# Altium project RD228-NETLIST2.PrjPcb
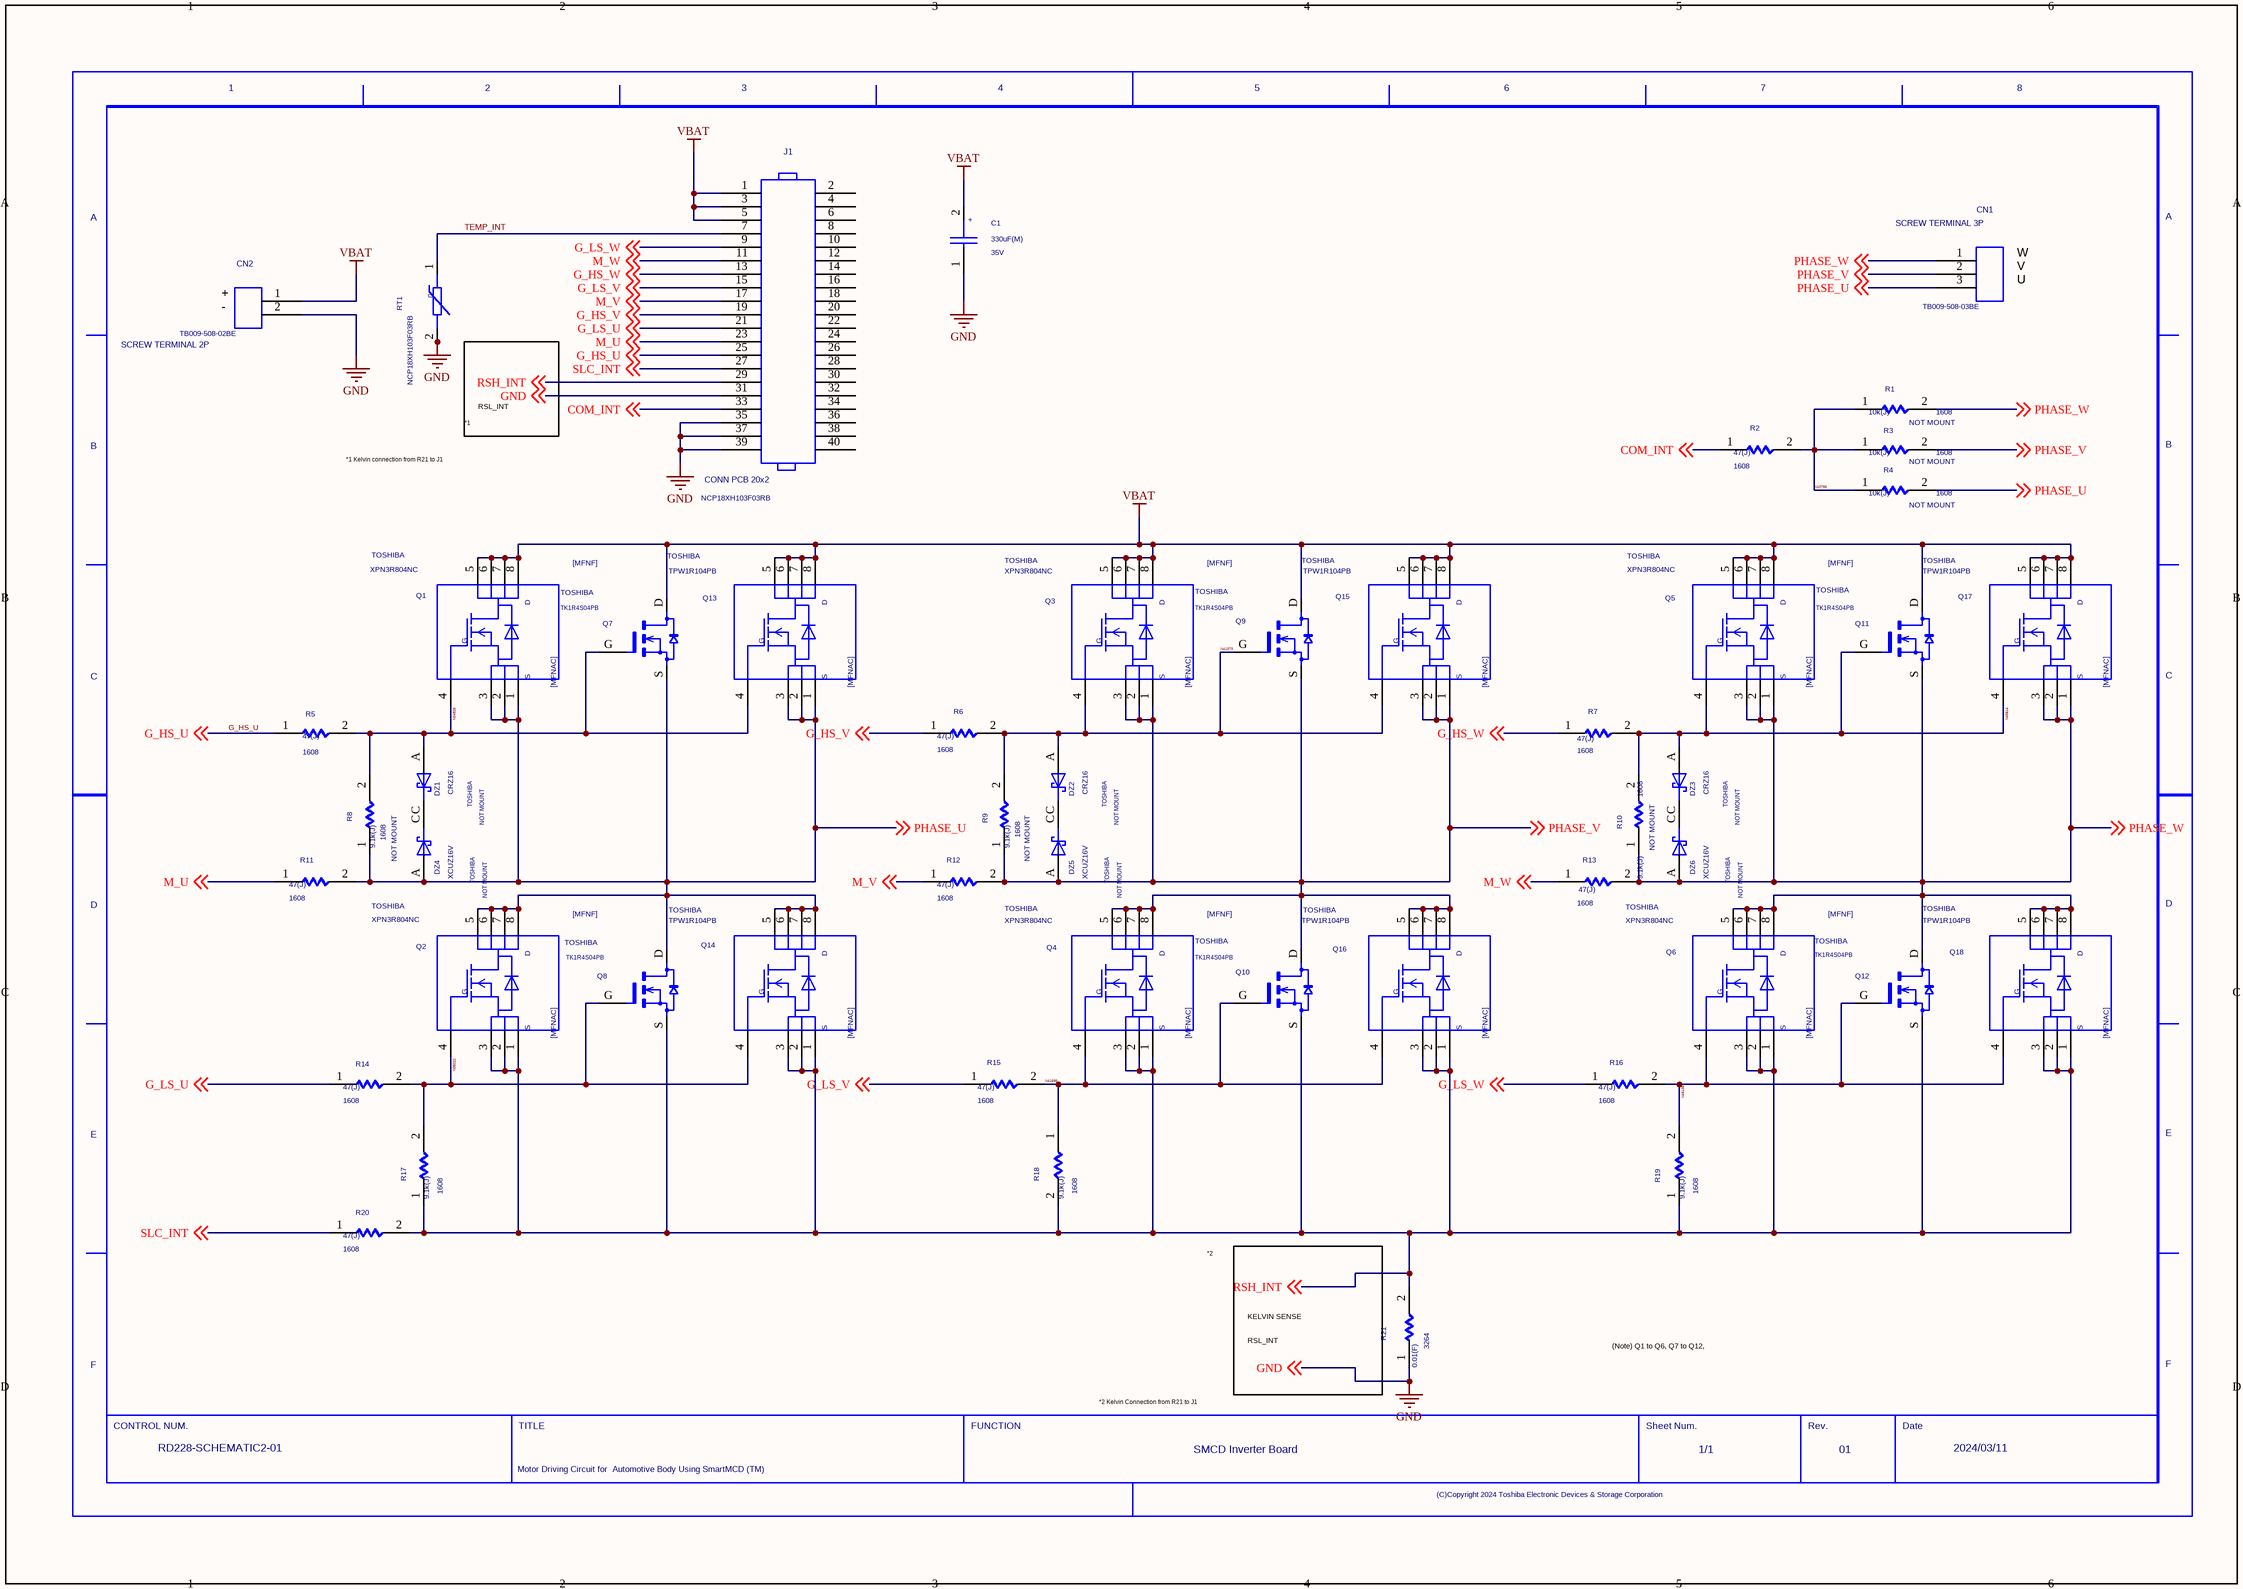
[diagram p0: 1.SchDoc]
1 sheet, 51 parts. Net scope: global (net labels, ports and power ports of the same name join across sheets).

## Sheet 1.SchDoc
size 420 x 297 mm

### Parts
C1  VAL2: 35V  VAL1: 330uF(M)  (hidden comment: CP)
CN1  SCREW TERMINAL 3P  VAL3: TB009-508-03BE
CN2  SCREW TERMINAL 2P  COMP: TB009-508-02BE
DZ1  NOTMOUNT: NOT MOUNT  USERCOMPTEXT3: TOSHIBA  VAL3: CRZ16  (hidden comment: SBD)
DZ2  NOTMOUNT: NOT MOUNT  USERCOMPTEXT3: TOSHIBA  VAL3: CRZ16  (hidden comment: SBD)
DZ3  NOTMOUNT: NOT MOUNT  USERCOMPTEXT3: TOSHIBA  VAL3: CRZ16  (hidden comment: SBD)
DZ4  NOTMOUNT: NOT MOUNT  USERCOMPTEXT3: TOSHIBA  VAL3: XCUZ16V  (hidden comment: SBD)
DZ5  NOTMOUNT: NOT MOUNT  USERCOMPTEXT3: TOSHIBA  VAL3: XCUZ16V  (hidden comment: SBD)
DZ6  NOTMOUNT: NOT MOUNT  USERCOMPTEXT3: TOSHIBA  VAL3: XCUZ16V  (hidden comment: SBD)
J1  CONN PCB 20x2  COMP: NCP18XH103F03RB
Q1  USERCOMPTEXT3: TOSHIBA  VAL3: XPN3R804NC  (hidden comment: MFNAC)
Q2  USERCOMPTEXT3: TOSHIBA  VAL3: XPN3R804NC  (hidden comment: MFNAC)
Q3  USERCOMPTEXT3: TOSHIBA  VAL3: XPN3R804NC  (hidden comment: MFNAC)
Q4  USERCOMPTEXT3: TOSHIBA  VAL3: XPN3R804NC  (hidden comment: MFNAC)
Q5  USERCOMPTEXT3: TOSHIBA  VAL3: XPN3R804NC  (hidden comment: MFNAC)
Q6  USERCOMPTEXT3: TOSHIBA  VAL3: XPN3R804NC  (hidden comment: MFNAC)
Q7  USERCOMPTEXT3: TOSHIBA  VAL3: TK1R4S04PB  (hidden comment: MFNF)
Q8  USERCOMPTEXT3: TOSHIBA  VAL3: TK1R4S04PB  (hidden comment: MFNF)
Q9  USERCOMPTEXT3: TOSHIBA  VAL3: TK1R4S04PB  (hidden comment: MFNF)
Q10  USERCOMPTEXT3: TOSHIBA  VAL3: TK1R4S04PB  (hidden comment: MFNF)
Q11  USERCOMPTEXT3: TOSHIBA  VAL3: TK1R4S04PB  (hidden comment: MFNF)
Q12  USERCOMPTEXT3: TOSHIBA  VAL3: TK1R4S04PB  (hidden comment: MFNF)
Q13  USERCOMPTEXT3: TOSHIBA  VAL3: TPW1R104PB  (hidden comment: MFNAC)
Q14  USERCOMPTEXT3: TOSHIBA  VAL3: TPW1R104PB  (hidden comment: MFNAC)
Q15  USERCOMPTEXT3: TOSHIBA  VAL3: TPW1R104PB  (hidden comment: MFNAC)
Q16  USERCOMPTEXT3: TOSHIBA  VAL3: TPW1R104PB  (hidden comment: MFNAC)
Q17  USERCOMPTEXT3: TOSHIBA  VAL3: TPW1R104PB  (hidden comment: MFNAC)
Q18  USERCOMPTEXT3: TOSHIBA  VAL3: TPW1R104PB  (hidden comment: MFNAC)
R1  NOTMOUNT: NOT MOUNT  SIZECODESMD: 1608  VAL1: 10k(J)  (hidden comment: R)
R2  SIZECODESMD: 1608  VAL1: 47(J)  (hidden comment: R)
R3  NOTMOUNT: NOT MOUNT  SIZECODESMD: 1608  VAL1: 10k(J)  (hidden comment: R)
R4  NOTMOUNT: NOT MOUNT  SIZECODESMD: 1608  VAL1: 10k(J)  (hidden comment: R)
R5  SIZECODESMD: 1608  VAL1: 47(J)  (hidden comment: R)
R6  SIZECODESMD: 1608  VAL1: 47(J)  (hidden comment: R)
R7  SIZECODESMD: 1608  VAL1: 47(J)  (hidden comment: R)
R8  NOTMOUNT: NOT MOUNT  SIZECODESMD: 1608  VAL1: 9.1k(J)  (hidden comment: R)
R9  NOTMOUNT: NOT MOUNT  SIZECODESMD: 1608  VAL1: 9.1k(J)  (hidden comment: R)
R10  NOTMOUNT: NOT MOUNT  SIZECODESMD: 1608  VAL1: 9.1k(J)  (hidden comment: R)
R11  SIZECODESMD: 1608  VAL1: 47(J)  (hidden comment: R)
R12  SIZECODESMD: 1608  VAL1: 47(J)  (hidden comment: R)
R13  SIZECODESMD: 1608  VAL1: 47(J)  (hidden comment: R)
R14  SIZECODESMD: 1608  VAL1: 47(J)  (hidden comment: R)
R15  SIZECODESMD: 1608  VAL1: 47(J)  (hidden comment: R)
R16  SIZECODESMD: 1608  VAL1: 47(J)  (hidden comment: R)
R17  SIZECODESMD: 1608  VAL1: 9.1k(J)  (hidden comment: R)
R18  SIZECODESMD: 1608  VAL1: 9.1k(J)  (hidden comment: R)
R19  SIZECODESMD: 1608  VAL1: 9.1k(J)  (hidden comment: R)
R20  SIZECODESMD: 1608  VAL1: 47(J)  (hidden comment: R)
R21  SIZECODESMD: 3264  VAL1: 0.01(F)  (hidden comment: R)
RT1  VAL3: NCP18XH103F03RB  (hidden comment: VARA)
U3  DATE: 2024/03/11  DRAWINGNUMBER: RD228-SCHEMATIC2-01  REVISION: 01  TITLE: Motor Driving Circuit for / Automotive Body Using SmartMCD (TM)  SHEETNUMBER: 1/1  FUNCTION: SMCD Inverter Board  (hidden comment: WAKU_DEF100)

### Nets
GND: C1.1 CN2.2 J1.31 J1.35 J1.37 J1.39 R21.1 RT1.2 ; off-sheet GND
VBAT: C1.2 CN2.1 J1.1 J1.3 J1.5 Q1.5 Q1.6 Q1.7 Q1.8 Q3.5 Q3.6 Q3.7 Q3.8 Q5.5 Q5.6 Q5.7 Q5.8 Q7.D Q9.D Q11.D Q13.5 Q13.6 Q13.7 Q13.8 Q15.5 Q15.6 Q15.7 Q15.8 Q17.5 Q17.6 Q17.7 Q17.8
COM_INT: J1.33 R2.1 ; off-sheet COM_INT
G_HS_U: J1.25 R5.1 ; off-sheet G_HS_U
G_HS_V: J1.19 R6.1 ; off-sheet G_HS_V
G_HS_W: J1.13 R7.1 ; off-sheet G_HS_W
G_LS_U: J1.21 R14.1 ; off-sheet G_LS_U
G_LS_V: J1.15 R15.1 ; off-sheet G_LS_V
G_LS_W: J1.9 R16.1 ; off-sheet G_LS_W
M_U: J1.23 R11.1 ; off-sheet M_U
M_V: J1.17 R12.1 ; off-sheet M_V
M_W: J1.11 R13.1 ; off-sheet M_W
N04926: DZ1.A Q1.4 Q7.G Q13.4 R5.2 R8.2
N05022: Q2.4 Q8.G Q14.4 R14.2 R17.2
N10786: R1.1 R2.2 R3.1 R4.1
N41373: DZ2.A Q3.4 Q9.G Q15.4 R6.2 R9.2
N41695: Q4.4 Q10.G Q16.4 R15.2 R18.1
N45814: DZ3.A Q5.4 Q11.G Q17.4 R7.2 R10.2
N46136: Q6.4 Q12.G Q18.4 R16.2 R19.2
PHASE_U: CN1.3 DZ4.A Q1.1 Q1.2 Q1.3 Q2.5 Q2.6 Q2.7 Q2.8 Q7.S Q8.D Q13.1 Q13.2 Q13.3 Q14.5 Q14.6 Q14.7 Q14.8 R4.2 R8.1 R11.2 ; off-sheet PHASE_U
PHASE_V: CN1.2 DZ5.A Q3.1 Q3.2 Q3.3 Q4.5 Q4.6 Q4.7 Q4.8 Q9.S Q10.D Q15.1 Q15.2 Q15.3 Q16.5 Q16.6 Q16.7 Q16.8 R3.2 R9.1 R12.2 ; off-sheet PHASE_V
PHASE_W: CN1.1 DZ6.A Q5.1 Q5.2 Q5.3 Q6.5 Q6.6 Q6.7 Q6.8 Q11.S Q12.D Q17.1 Q17.2 Q17.3 Q18.5 Q18.6 Q18.7 Q18.8 R1.2 R10.1 R13.2 ; off-sheet PHASE_W
RSH_INT: J1.29 Q2.1 Q2.2 Q2.3 Q4.1 Q4.2 Q4.3 Q6.1 Q6.2 Q6.3 Q8.S Q10.S Q12.S Q14.1 Q14.2 Q14.3 Q16.1 Q16.2 Q16.3 Q18.1 Q18.2 Q18.3 R17.1 R18.2 R19.1 R20.2 R21.2 ; off-sheet RSH_INT
SLC_INT: J1.27 R20.1 ; off-sheet SLC_INT
TEMP_INT: J1.7 RT1.1
NetDZ1_C: DZ1.C DZ4.C
NetDZ2_C: DZ2.C DZ5.C
NetDZ3_C: DZ3.C DZ6.C

Not connected (* = marked no-connect by the designer): J1 2 4 6 8 10 12 14 16 18 20 22 24 26 28 30 32 34 36 38 40

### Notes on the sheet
- (near CN1) W
- (near CN2) +
- (near CN2) -
- (near CN1) V
- (near CN1) U
- *1 Kelvin connection from R21 to J1
- *1
- RSL_INT
- *2
- KELVIN SENSE
- *2 Kelvin Connection from R21 to J1
- (Note) Q1 to Q6, Q7 to Q12,
  and Q13 to Q18 are exclusively mounted.
  XPH2R404PS also can be used for Q13 to Q18.

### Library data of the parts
C1 = CP: OUMEPARTTYPE: C; TIME: 15:02:55; UPDATEUSER: fukuda-y; UPDATETIME: 16:13:42; SAVECOUNT: 52; COMP: PRT_4; SAVEAREA0: -1450,-153,20294,13055; ORIGINALSYMBOLORIGIN: (0,0); __TIME_0__: 1708057012; __USER_0__: t5459927; __FILE_0__: C:/Users/t5459927/Desktop/test_ORCtoSD/RD228-SCHEMATIC2-01/SMB006/CP.smb; __HOST_0__: t5459927-02; __$Database_ID__: Z-b3d26258-3a88-4599-b1c4-1147a8743763; LAYOUTNAME: Z-4fe26e2d-0314-4a28-872c-3bd199d55978.cmp38; COMPONENTNAME: CP_CP; QUADMODEL: CON_330U; NOMINALCAPACITA: 330u; RATEDVOLTAGE: 450; CDMASTERCADCELG: DC213N; MAKER: RUBYCON; GCOUNT: 1; SIZECODESMD: DIP; OUMEMAKER: SIT ルビコン; VAL4: Panasonic; FNLEADFREETHET1GT2GMCTH1: 9_N_N; VAL3: EEE-FN1V331UP; CAPACITANCETOLE: M; OUMECLASSIFICATION: アルミ電解コンデンサ; OUMEMAKERKATAMEI: 450MXC330M35X40; CHIPSIZE: D35xL30; INSTANCENAME: INS16733
CN1 = CON3: TIME: 13:16:52; UPDATEUSER: t5459927; SAVECOUNT: 2; __TIME_0__: 1708057012; __FILE_0__: C:/Users/t5459927/Desktop/test_ORCtoSD/RD228-SCHEMATIC2-01/CONNECTOR/CON3.smb; __HOST_0__: t5459927-02; __$Database_ID__: Z-e328b140-1b63-4e28-8335-8379fb4ab7a1; OriginalSymbolOrigin: (0,0); LAYOUTNAME: Z-4fe26e2d-0314-4a28-872c-3bd199d55978.cmp14; COMPONENTNAME: CON3_CON3; VAL4: CUI Devices; INSTANCENAME: INS12037
CN2 = CON2: TIME: 13:16:52; UPDATEUSER: t5459927; SAVECOUNT: 2; __TIME_0__: 1708057012; __FILE_0__: C:/Users/t5459927/Desktop/test_ORCtoSD/RD228-SCHEMATIC2-01/CONNECTOR/CON2.smb; __HOST_0__: t5459927-02; __$Database_ID__: Z-c5718943-9b6a-4755-a070-3d61e98e6b47; OriginalSymbolOrigin: (0,0); LAYOUTNAME: Z-4fe26e2d-0314-4a28-872c-3bd199d55978.cmp16; COMPONENTNAME: CON2_CON2; VAL4: CUI Devices; INSTANCENAME: INS65872
DZ1-DZ3 = SBD: SAVEAREA0: -4630,-153,17114,13055; TIME: 14:49:55; UPDATEUSER: fukuda-y; UPDATETIME: 08:16:22; SAVECOUNT: 9; OriginalSymbolOrigin: (5080,5080); COMPONENTNAME: SBD_SBD; INSTANCENAME: INS75512; NUMBER DEVICES IN PACKAGE: 1; PIN NUMBERS VISIBLE: True; PIN NAMES VISIBLE: False
DZ4-DZ6 = SBD: SAVEAREA0: -4630,-153,17114,13055; TIME: 14:49:55; UPDATEUSER: fukuda-y; UPDATETIME: 08:16:22; SAVECOUNT: 9; OriginalSymbolOrigin: (5080,5080); COMPONENTNAME: SBD_SBD; INSTANCENAME: INS75524; NUMBER DEVICES IN PACKAGE: 1; PIN NUMBERS VISIBLE: True; PIN NAMES VISIBLE: False
J1 = CONN_PCB_20X2_0: TIME: 13:16:52; UPDATEUSER: t5459927; SAVECOUNT: 3; OriginalSymbolOrigin: (0,0); LAYOUTNAME: Z-4fe26e2d-0314-4a28-872c-3bd199d55978.cmp27; COMPONENTNAME: CONN_PCB_20x2_0_CONN_PCB_20x2_0; VAL4: TE Connectivity; VAL3: 7-534206-0; INSTANCENAME: INS11476
Q1 = MFNAC: TIME: 18:29:30; UPDATEUSER: 19990028; UPDATETIME: 14:45:16; SAVECOUNT: 26; COMP: PRT_67; SAVEAREA0: -10143,-336,37609,28718; ORIGINALSYMBOLORIGIN: (0,0); __TIME_0__: 1708057012; __USER_0__: t5459927; __FILE_0__: C:/Users/t5459927/Desktop/test_ORCtoSD/RD228-SCHEMATIC2-01/SMB005/MFNAC.smb; __HOST_0__: t5459927-02; __$Database_ID__: Z-b863f03c-2bf8-4525-9966-7b6b866df037; LAYOUTNAME: Z-4fe26e2d-0314-4a28-872c-3bd199d55978.cmp44; COMPONENTNAME: MFNAC_MFNAC; INSTANCENAME: INS28653
Q2 = MFNAC: TIME: 18:29:30; UPDATEUSER: 19990028; UPDATETIME: 14:45:16; SAVECOUNT: 26; COMP: PRT_67; SAVEAREA0: -10143,-336,37609,28718; ORIGINALSYMBOLORIGIN: (0,0); __TIME_0__: 1708057012; __USER_0__: t5459927; __FILE_0__: C:/Users/t5459927/Desktop/test_ORCtoSD/RD228-SCHEMATIC2-01/SMB005/MFNAC.smb; __HOST_0__: t5459927-02; __$Database_ID__: Z-b863f03c-2bf8-4525-9966-7b6b866df037; LAYOUTNAME: Z-4fe26e2d-0314-4a28-872c-3bd199d55978.cmp3; COMPONENTNAME: MFNAC_MFNAC; INSTANCENAME: INS31297
Q3 = MFNAC: TIME: 18:29:30; UPDATEUSER: 19990028; UPDATETIME: 14:45:16; SAVECOUNT: 26; COMP: PRT_67; SAVEAREA0: -10143,-336,37609,28718; ORIGINALSYMBOLORIGIN: (0,0); __TIME_0__: 1708057012; __USER_0__: t5459927; __FILE_0__: C:/Users/t5459927/Desktop/test_ORCtoSD/RD228-SCHEMATIC2-01/SMB005/MFNAC.smb; __HOST_0__: t5459927-02; __$Database_ID__: Z-b863f03c-2bf8-4525-9966-7b6b866df037; LAYOUTNAME: Z-4fe26e2d-0314-4a28-872c-3bd199d55978.cmp10; COMPONENTNAME: MFNAC_MFNAC; INSTANCENAME: INS41315
Q4 = MFNAC: TIME: 18:29:30; UPDATEUSER: 19990028; UPDATETIME: 14:45:16; SAVECOUNT: 26; COMP: PRT_67; SAVEAREA0: -10143,-336,37609,28718; ORIGINALSYMBOLORIGIN: (0,0); __TIME_0__: 1708057012; __USER_0__: t5459927; __FILE_0__: C:/Users/t5459927/Desktop/test_ORCtoSD/RD228-SCHEMATIC2-01/SMB005/MFNAC.smb; __HOST_0__: t5459927-02; __$Database_ID__: Z-b863f03c-2bf8-4525-9966-7b6b866df037; LAYOUTNAME: Z-4fe26e2d-0314-4a28-872c-3bd199d55978.cmp23; COMPONENTNAME: MFNAC_MFNAC; INSTANCENAME: INS41637
Q5 = MFNAC: TIME: 18:29:30; UPDATEUSER: 19990028; UPDATETIME: 14:45:16; SAVECOUNT: 26; COMP: PRT_67; SAVEAREA0: -10143,-336,37609,28718; ORIGINALSYMBOLORIGIN: (0,0); __TIME_0__: 1708057012; __USER_0__: t5459927; __FILE_0__: C:/Users/t5459927/Desktop/test_ORCtoSD/RD228-SCHEMATIC2-01/SMB005/MFNAC.smb; __HOST_0__: t5459927-02; __$Database_ID__: Z-b863f03c-2bf8-4525-9966-7b6b866df037; LAYOUTNAME: Z-4fe26e2d-0314-4a28-872c-3bd199d55978.cmp8; COMPONENTNAME: MFNAC_MFNAC; INSTANCENAME: INS45756
Q6 = MFNAC: TIME: 18:29:30; UPDATEUSER: 19990028; UPDATETIME: 14:45:16; SAVECOUNT: 26; COMP: PRT_67; SAVEAREA0: -10143,-336,37609,28718; ORIGINALSYMBOLORIGIN: (0,0); __TIME_0__: 1708057012; __USER_0__: t5459927; __FILE_0__: C:/Users/t5459927/Desktop/test_ORCtoSD/RD228-SCHEMATIC2-01/SMB005/MFNAC.smb; __HOST_0__: t5459927-02; __$Database_ID__: Z-b863f03c-2bf8-4525-9966-7b6b866df037; LAYOUTNAME: Z-4fe26e2d-0314-4a28-872c-3bd199d55978.cmp21; COMPONENTNAME: MFNAC_MFNAC; INSTANCENAME: INS46078
Q7 = MFNF: TIME: 13:16:52; UPDATEUSER: t5459927; SAVECOUNT: 11; SAVEAREA0: -7027,-292,21786,15988; ORIGINALSYMBOLORIGIN: (0,0); __TIME_0__: 1708057012; __FILE_0__: C:/Users/t5459927/Desktop/test_ORCtoSD/RD228-SCHEMATIC2-01/SMB005/MFNF.smb; __HOST_0__: t5459927-02; __$Database_ID__: Z-a01eb178-07fb-446e-81a1-5aa5c84bcce8; LAYOUTNAME: Z-4fe26e2d-0314-4a28-872c-3bd199d55978.cmp32; COMPONENTNAME: MFNF_MFNF; INSTANCENAME: INS28533
Q8 = MFNF: TIME: 13:16:52; UPDATEUSER: t5459927; SAVECOUNT: 11; SAVEAREA0: -7027,-292,21786,15988; ORIGINALSYMBOLORIGIN: (0,0); COMP: PRT_9; __TIME_0__: 1708057012; __FILE_0__: C:/Users/t5459927/Desktop/test_ORCtoSD/RD228-SCHEMATIC2-01/SMB005/MFNF.smb; __HOST_0__: t5459927-02; __$Database_ID__: Z-a01eb178-07fb-446e-81a1-5aa5c84bcce8; LAYOUTNAME: Z-4fe26e2d-0314-4a28-872c-3bd199d55978.cmp20; COMPONENTNAME: MFNF_MFNF; INSTANCENAME: INS31341
Q9 = MFNF: TIME: 13:16:52; UPDATEUSER: t5459927; SAVECOUNT: 11; SAVEAREA0: -7027,-292,21786,15988; ORIGINALSYMBOLORIGIN: (0,0); COMP: PRT_9; __TIME_0__: 1708057012; __FILE_0__: C:/Users/t5459927/Desktop/test_ORCtoSD/RD228-SCHEMATIC2-01/SMB005/MFNF.smb; __HOST_0__: t5459927-02; __$Database_ID__: Z-a01eb178-07fb-446e-81a1-5aa5c84bcce8; LAYOUTNAME: Z-4fe26e2d-0314-4a28-872c-3bd199d55978.cmp31; COMPONENTNAME: MFNF_MFNF; INSTANCENAME: INS41359
Q10 = MFNF: TIME: 13:16:52; UPDATEUSER: t5459927; SAVECOUNT: 11; SAVEAREA0: -7027,-292,21786,15988; ORIGINALSYMBOLORIGIN: (0,0); COMP: PRT_9; __TIME_0__: 1708057012; __FILE_0__: C:/Users/t5459927/Desktop/test_ORCtoSD/RD228-SCHEMATIC2-01/SMB005/MFNF.smb; __HOST_0__: t5459927-02; __$Database_ID__: Z-a01eb178-07fb-446e-81a1-5aa5c84bcce8; LAYOUTNAME: Z-4fe26e2d-0314-4a28-872c-3bd199d55978.cmp40; COMPONENTNAME: MFNF_MFNF; INSTANCENAME: INS41681
Q11 = MFNF: TIME: 13:16:52; UPDATEUSER: t5459927; SAVECOUNT: 11; SAVEAREA0: -7027,-292,21786,15988; ORIGINALSYMBOLORIGIN: (0,0); COMP: PRT_9; __TIME_0__: 1708057012; __FILE_0__: C:/Users/t5459927/Desktop/test_ORCtoSD/RD228-SCHEMATIC2-01/SMB005/MFNF.smb; __HOST_0__: t5459927-02; __$Database_ID__: Z-a01eb178-07fb-446e-81a1-5aa5c84bcce8; LAYOUTNAME: Z-4fe26e2d-0314-4a28-872c-3bd199d55978.cmp29; COMPONENTNAME: MFNF_MFNF; INSTANCENAME: INS45800
Q12 = MFNF: TIME: 13:16:52; UPDATEUSER: t5459927; SAVECOUNT: 11; SAVEAREA0: -7027,-292,21786,15988; ORIGINALSYMBOLORIGIN: (0,0); COMP: PRT_9; __TIME_0__: 1708057012; __FILE_0__: C:/Users/t5459927/Desktop/test_ORCtoSD/RD228-SCHEMATIC2-01/SMB005/MFNF.smb; __HOST_0__: t5459927-02; __$Database_ID__: Z-a01eb178-07fb-446e-81a1-5aa5c84bcce8; LAYOUTNAME: Z-4fe26e2d-0314-4a28-872c-3bd199d55978.cmp39; COMPONENTNAME: MFNF_MFNF; INSTANCENAME: INS46122
Q13 = MFNAC: TIME: 18:29:30; UPDATEUSER: 19990028; UPDATETIME: 14:45:16; SAVECOUNT: 26; SAVEAREA0: -10143,-336,37609,28718; ORIGINALSYMBOLORIGIN: (0,0); __TIME_0__: 1708057012; __USER_0__: t5459927; __FILE_0__: C:/Users/t5459927/Desktop/test_ORCtoSD/RD228-SCHEMATIC2-01/SMB005/MFNAC.smb; __HOST_0__: t5459927-02; __$Database_ID__: Z-b863f03c-2bf8-4525-9966-7b6b866df037; LAYOUTNAME: Z-4fe26e2d-0314-4a28-872c-3bd199d55978.cmp30; COMPCOMMENT: XPH2R404PS; COMPONENTNAME: MFNAC_MFNAC; INSTANCENAME: INS28724
Q14 = MFNAC: TIME: 18:29:30; UPDATEUSER: 19990028; UPDATETIME: 14:45:16; SAVECOUNT: 26; COMP: PRT_67; SAVEAREA0: -10143,-336,37609,28718; ORIGINALSYMBOLORIGIN: (0,0); __TIME_0__: 1708057012; __USER_0__: t5459927; __FILE_0__: C:/Users/t5459927/Desktop/test_ORCtoSD/RD228-SCHEMATIC2-01/SMB005/MFNAC.smb; __HOST_0__: t5459927-02; __$Database_ID__: Z-b863f03c-2bf8-4525-9966-7b6b866df037; LAYOUTNAME: Z-4fe26e2d-0314-4a28-872c-3bd199d55978.cmp12; COMPCOMMENT: XPH2R404PS; COMPONENTNAME: MFNAC_MFNAC; INSTANCENAME: INS31319
Q15 = MFNAC: TIME: 18:29:30; UPDATEUSER: 19990028; UPDATETIME: 14:45:16; SAVECOUNT: 26; COMP: PRT_67; SAVEAREA0: -10143,-336,37609,28718; ORIGINALSYMBOLORIGIN: (0,0); __TIME_0__: 1708057012; __USER_0__: t5459927; __FILE_0__: C:/Users/t5459927/Desktop/test_ORCtoSD/RD228-SCHEMATIC2-01/SMB005/MFNAC.smb; __HOST_0__: t5459927-02; __$Database_ID__: Z-b863f03c-2bf8-4525-9966-7b6b866df037; LAYOUTNAME: Z-4fe26e2d-0314-4a28-872c-3bd199d55978.cmp26; COMPCOMMENT: XPH2R404PS; COMPONENTNAME: MFNAC_MFNAC; INSTANCENAME: INS41337
Q16 = MFNAC: TIME: 18:29:30; UPDATEUSER: 19990028; UPDATETIME: 14:45:16; SAVECOUNT: 26; COMP: PRT_67; SAVEAREA0: -10143,-336,37609,28718; ORIGINALSYMBOLORIGIN: (0,0); __TIME_0__: 1708057012; __USER_0__: t5459927; __FILE_0__: C:/Users/t5459927/Desktop/test_ORCtoSD/RD228-SCHEMATIC2-01/SMB005/MFNAC.smb; __HOST_0__: t5459927-02; __$Database_ID__: Z-b863f03c-2bf8-4525-9966-7b6b866df037; LAYOUTNAME: Z-4fe26e2d-0314-4a28-872c-3bd199d55978.cmp34; COMPCOMMENT: XPH2R404PS; COMPONENTNAME: MFNAC_MFNAC; INSTANCENAME: INS41659
Q17 = MFNAC: TIME: 18:29:30; UPDATEUSER: 19990028; UPDATETIME: 14:45:16; SAVECOUNT: 26; COMP: PRT_67; SAVEAREA0: -10143,-336,37609,28718; ORIGINALSYMBOLORIGIN: (0,0); __TIME_0__: 1708057012; __USER_0__: t5459927; __FILE_0__: C:/Users/t5459927/Desktop/test_ORCtoSD/RD228-SCHEMATIC2-01/SMB005/MFNAC.smb; __HOST_0__: t5459927-02; __$Database_ID__: Z-b863f03c-2bf8-4525-9966-7b6b866df037; LAYOUTNAME: Z-4fe26e2d-0314-4a28-872c-3bd199d55978.cmp22; COMPCOMMENT: XPH2R404PS; COMPONENTNAME: MFNAC_MFNAC; INSTANCENAME: INS45778
Q18 = MFNAC: TIME: 18:29:30; UPDATEUSER: 19990028; UPDATETIME: 14:45:16; SAVECOUNT: 26; COMP: PRT_67; SAVEAREA0: -10143,-336,37609,28718; ORIGINALSYMBOLORIGIN: (0,0); __TIME_0__: 1708057012; __USER_0__: t5459927; __FILE_0__: C:/Users/t5459927/Desktop/test_ORCtoSD/RD228-SCHEMATIC2-01/SMB005/MFNAC.smb; __HOST_0__: t5459927-02; __$Database_ID__: Z-b863f03c-2bf8-4525-9966-7b6b866df037; LAYOUTNAME: Z-4fe26e2d-0314-4a28-872c-3bd199d55978.cmp33; COMPCOMMENT: XPH2R404PS; COMPONENTNAME: MFNAC_MFNAC; INSTANCENAME: INS46100
R1 = R: TIME: 13:16:51; UPDATEUSER: t5459927; SAVECOUNT: 2; ORIGINALSYMBOLORIGIN: (0,0); COMP: PRT_5; __TIME_0__: 1708057011; __FILE_0__: C:/Users/t5459927/Desktop/test_ORCtoSD/RD228-SCHEMATIC2-01/SMB007/R.smb; __HOST_0__: t5459927-02; __$Database_ID__: Z-1d8715ec-4297-42d6-bed7-916b1ffe081f; LAYOUTNAME: Z-4fe26e2d-0314-4a28-872c-3bd199d55978.cmp9; COMPONENTNAME: R_R; RESISTANCETOLER: J; FNLEADFREETHET1GT2GMCTH1: N_N_N; NOMINALRESISTAN: 1m; POWERRATING: 500m; ADSMODELNAME: s_RL1632H_R001_JN; OUMEMAKER: SSM 進工業; VAL4: KOA; OUMECLASSIFICATION: 表面実装用固定抵抗器; VAL3: RK73B1ETTP103J; MOUNTINGFORMSMD: SMD; VAL2: 0.1W; OUMEMAKERKATAMEI: RL1632H-R001-JN; CDMASTERCADCELG: KC0020; QUADMODEL: RES_1M; GCOUNT: 1; CHIPSIZE: 3216; INSTANCENAME: INS10722
R2 = R: TIME: 13:16:51; UPDATEUSER: t5459927; SAVECOUNT: 2; ORIGINALSYMBOLORIGIN: (0,0); COMP: PRT_5; __TIME_0__: 1708057011; __FILE_0__: C:/Users/t5459927/Desktop/test_ORCtoSD/RD228-SCHEMATIC2-01/SMB007/R.smb; __HOST_0__: t5459927-02; __$Database_ID__: Z-1d8715ec-4297-42d6-bed7-916b1ffe081f; LAYOUTNAME: Z-4fe26e2d-0314-4a28-872c-3bd199d55978.cmp28; COMPONENTNAME: R_R; RESISTANCETOLER: J; FNLEADFREETHET1GT2GMCTH1: N_N_N; NOMINALRESISTAN: 1m; POWERRATING: 500m; ADSMODELNAME: s_RL1632H_R001_JN; OUMEMAKER: SSM 進工業; VAL4: KOA; OUMECLASSIFICATION: 表面実装用固定抵抗器; VAL3: RK73B1ETTP470J; MOUNTINGFORMSMD: SMD; VAL2: 0.1W; OUMEMAKERKATAMEI: RL1632H-R001-JN; CDMASTERCADCELG: KC0020; QUADMODEL: RES_1M; GCOUNT: 1; CHIPSIZE: 3216; INSTANCENAME: INS10855
R3 = R: TIME: 13:16:51; UPDATEUSER: t5459927; SAVECOUNT: 2; ORIGINALSYMBOLORIGIN: (0,0); COMP: PRT_5; __TIME_0__: 1708057011; __FILE_0__: C:/Users/t5459927/Desktop/test_ORCtoSD/RD228-SCHEMATIC2-01/SMB007/R.smb; __HOST_0__: t5459927-02; __$Database_ID__: Z-1d8715ec-4297-42d6-bed7-916b1ffe081f; LAYOUTNAME: Z-4fe26e2d-0314-4a28-872c-3bd199d55978.cmp24; COMPONENTNAME: R_R; RESISTANCETOLER: J; FNLEADFREETHET1GT2GMCTH1: N_N_N; NOMINALRESISTAN: 1m; POWERRATING: 500m; ADSMODELNAME: s_RL1632H_R001_JN; OUMEMAKER: SSM 進工業; VAL4: KOA; OUMECLASSIFICATION: 表面実装用固定抵抗器; VAL3: RK73B1ETTP103J; MOUNTINGFORMSMD: SMD; VAL2: 0.1W; OUMEMAKERKATAMEI: RL1632H-R001-JN; CDMASTERCADCELG: KC0020; QUADMODEL: RES_1M; GCOUNT: 1; CHIPSIZE: 3216; INSTANCENAME: INS10744
R4 = R: TIME: 13:16:51; UPDATEUSER: t5459927; SAVECOUNT: 2; ORIGINALSYMBOLORIGIN: (0,0); COMP: PRT_5; __TIME_0__: 1708057011; __FILE_0__: C:/Users/t5459927/Desktop/test_ORCtoSD/RD228-SCHEMATIC2-01/SMB007/R.smb; __HOST_0__: t5459927-02; __$Database_ID__: Z-1d8715ec-4297-42d6-bed7-916b1ffe081f; LAYOUTNAME: Z-4fe26e2d-0314-4a28-872c-3bd199d55978.cmp35; COMPONENTNAME: R_R; RESISTANCETOLER: J; FNLEADFREETHET1GT2GMCTH1: N_N_N; NOMINALRESISTAN: 1m; POWERRATING: 500m; ADSMODELNAME: s_RL1632H_R001_JN; OUMEMAKER: SSM 進工業; VAL4: KOA; OUMECLASSIFICATION: 表面実装用固定抵抗器; VAL3: RK73B1ETTP103J; MOUNTINGFORMSMD: SMD; VAL2: 0.1W; OUMEMAKERKATAMEI: RL1632H-R001-JN; CDMASTERCADCELG: KC0020; QUADMODEL: RES_1M; GCOUNT: 1; CHIPSIZE: 3216; INSTANCENAME: INS10766
R5 = R: TIME: 13:16:51; UPDATEUSER: t5459927; SAVECOUNT: 2; ORIGINALSYMBOLORIGIN: (0,0); COMP: PRT_5; __TIME_0__: 1708057011; __FILE_0__: C:/Users/t5459927/Desktop/test_ORCtoSD/RD228-SCHEMATIC2-01/SMB007/R.smb; __HOST_0__: t5459927-02; __$Database_ID__: Z-1d8715ec-4297-42d6-bed7-916b1ffe081f; LAYOUTNAME: Z-4fe26e2d-0314-4a28-872c-3bd199d55978.cmp25; COMPONENTNAME: R_R; RESISTANCETOLER: J; FNLEADFREETHET1GT2GMCTH1: N_N_N; NOMINALRESISTAN: 1m; POWERRATING: 500m; ADSMODELNAME: s_RL1632H_R001_JN; OUMEMAKER: SSM 進工業; VAL4: KOA; OUMECLASSIFICATION: 表面実装用固定抵抗器; VAL3: RK73B1JTTD470J; MOUNTINGFORMSMD: SMD; VAL2: 0.1W; OUMEMAKERKATAMEI: RL1632H-R001-JN; CDMASTERCADCELG: KC0020; QUADMODEL: RES_1M; GCOUNT: 1; CHIPSIZE: 3216; INSTANCENAME: INS6200
R6 = R: TIME: 13:16:51; UPDATEUSER: t5459927; SAVECOUNT: 2; ORIGINALSYMBOLORIGIN: (0,0); COMP: PRT_5; __TIME_0__: 1708057011; __FILE_0__: C:/Users/t5459927/Desktop/test_ORCtoSD/RD228-SCHEMATIC2-01/SMB007/R.smb; __HOST_0__: t5459927-02; __$Database_ID__: Z-1d8715ec-4297-42d6-bed7-916b1ffe081f; LAYOUTNAME: Z-4fe26e2d-0314-4a28-872c-3bd199d55978.cmp5; COMPONENTNAME: R_R; RESISTANCETOLER: J; FNLEADFREETHET1GT2GMCTH1: N_N_N; NOMINALRESISTAN: 1m; POWERRATING: 500m; ADSMODELNAME: s_RL1632H_R001_JN; OUMEMAKER: SSM 進工業; VAL4: KOA; OUMECLASSIFICATION: 表面実装用固定抵抗器; VAL3: RK73B1JTTD470J; MOUNTINGFORMSMD: SMD; VAL2: 0.1W; OUMEMAKERKATAMEI: RL1632H-R001-JN; CDMASTERCADCELG: KC0020; QUADMODEL: RES_1M; GCOUNT: 1; CHIPSIZE: 3216; INSTANCENAME: INS41415
R7 = R: TIME: 13:16:51; UPDATEUSER: t5459927; SAVECOUNT: 2; ORIGINALSYMBOLORIGIN: (0,0); __TIME_0__: 1708057011; __FILE_0__: C:/Users/t5459927/Desktop/test_ORCtoSD/RD228-SCHEMATIC2-01/SMB007/R.smb; __HOST_0__: t5459927-02; __$Database_ID__: Z-1d8715ec-4297-42d6-bed7-916b1ffe081f; LAYOUTNAME: Z-4fe26e2d-0314-4a28-872c-3bd199d55978.cmp4; VAL3: RK73B1JTTD470J; COMPONENTNAME: R_R; RESISTANCETOLER: J; FNLEADFREETHET1GT2GMCTH1: N_N_N; NOMINALRESISTAN: 1m; POWERRATING: 500m; ADSMODELNAME: s_RL1632H_R001_JN; OUMEMAKER: SSM 進工業; VAL4: KOA; OUMECLASSIFICATION: 表面実装用固定抵抗器; MOUNTINGFORMSMD: SMD; VAL2: 0.1W; OUMEMAKERKATAMEI: RL1632H-R001-JN; CDMASTERCADCELG: KC0020; QUADMODEL: RES_1M; GCOUNT: 1; CHIPSIZE: 3216; INSTANCENAME: INS45856
R8 = R: TIME: 13:16:51; UPDATEUSER: t5459927; SAVECOUNT: 2; ORIGINALSYMBOLORIGIN: (0,0); COMP: PRT_8; __TIME_0__: 1708057011; __FILE_0__: C:/Users/t5459927/Desktop/test_ORCtoSD/RD228-SCHEMATIC2-01/SMB007/R.smb; __HOST_0__: t5459927-02; __$Database_ID__: Z-1d8715ec-4297-42d6-bed7-916b1ffe081f; LAYOUTNAME: Z-4fe26e2d-0314-4a28-872c-3bd199d55978.cmp43; COMPONENTNAME: R_R; RESISTANCETOLER: J; FNLEADFREETHET1GT2GMCTH1: N_N_N; NOMINALRESISTAN: 10K; POWERRATING: 100m; ADSMODELNAME: s_RK73B1JTTD103J@@; OUMEMAKER: KOA コーア; VAL4: KOA; OUMECLASSIFICATION: 表面実装用固定抵抗器; VAL3: RK73B1ETTP912J; MOUNTINGFORMSMD: SMD; VAL2: 0.1W; OUMEMAKERKATAMEI: RK73B1JTTD103J@@; CDMASTERCADCELG: KC0133; QUADMODEL: RES_10K; GCOUNT: 1; INSTANCENAME: INS8565
R9 = R: TIME: 13:16:51; UPDATEUSER: t5459927; SAVECOUNT: 2; ORIGINALSYMBOLORIGIN: (0,0); COMP: PRT_8; __TIME_0__: 1708057011; __FILE_0__: C:/Users/t5459927/Desktop/test_ORCtoSD/RD228-SCHEMATIC2-01/SMB007/R.smb; __HOST_0__: t5459927-02; __$Database_ID__: Z-1d8715ec-4297-42d6-bed7-916b1ffe081f; LAYOUTNAME: Z-4fe26e2d-0314-4a28-872c-3bd199d55978.cmp1; COMPONENTNAME: R_R; RESISTANCETOLER: J; FNLEADFREETHET1GT2GMCTH1: N_N_N; NOMINALRESISTAN: 10K; POWERRATING: 100m; ADSMODELNAME: s_RK73B1JTTD103J@@; OUMEMAKER: KOA コーア; VAL4: KOA; OUMECLASSIFICATION: 表面実装用固定抵抗器; VAL3: RK73B1ETTP912J; MOUNTINGFORMSMD: SMD; VAL2: 0.1W; OUMEMAKERKATAMEI: RK73B1JTTD103J@@; CDMASTERCADCELG: KC0133; QUADMODEL: RES_10K; GCOUNT: 1; INSTANCENAME: INS41505
R10 = R: TIME: 13:16:51; UPDATEUSER: t5459927; SAVECOUNT: 2; ORIGINALSYMBOLORIGIN: (0,0); COMP: PRT_8; __TIME_0__: 1708057011; __FILE_0__: C:/Users/t5459927/Desktop/test_ORCtoSD/RD228-SCHEMATIC2-01/SMB007/R.smb; __HOST_0__: t5459927-02; __$Database_ID__: Z-1d8715ec-4297-42d6-bed7-916b1ffe081f; LAYOUTNAME: Z-4fe26e2d-0314-4a28-872c-3bd199d55978.cmp48; COMPONENTNAME: R_R; RESISTANCETOLER: J; FNLEADFREETHET1GT2GMCTH1: N_N_N; NOMINALRESISTAN: 10K; POWERRATING: 100m; ADSMODELNAME: s_RK73B1JTTD103J@@; OUMEMAKER: KOA コーア; VAL4: KOA; OUMECLASSIFICATION: 表面実装用固定抵抗器; VAL3: RK73B1ETTP912J; MOUNTINGFORMSMD: SMD; VAL2: 0.1W; OUMEMAKERKATAMEI: RK73B1JTTD103J@@; CDMASTERCADCELG: KC0133; QUADMODEL: RES_10K; GCOUNT: 1; INSTANCENAME: INS45946
R11 = R: TIME: 13:16:51; UPDATEUSER: t5459927; SAVECOUNT: 2; ORIGINALSYMBOLORIGIN: (0,0); COMP: PRT_5; __TIME_0__: 1708057011; __FILE_0__: C:/Users/t5459927/Desktop/test_ORCtoSD/RD228-SCHEMATIC2-01/SMB007/R.smb; __HOST_0__: t5459927-02; __$Database_ID__: Z-1d8715ec-4297-42d6-bed7-916b1ffe081f; LAYOUTNAME: Z-4fe26e2d-0314-4a28-872c-3bd199d55978.cmp51; COMPONENTNAME: R_R; RESISTANCETOLER: J; FNLEADFREETHET1GT2GMCTH1: N_N_N; NOMINALRESISTAN: 1m; POWERRATING: 500m; ADSMODELNAME: s_RL1632H_R001_JN; OUMEMAKER: SSM 進工業; VAL4: KOA; OUMECLASSIFICATION: 表面実装用固定抵抗器; VAL3: RK73B1JTTD470J; MOUNTINGFORMSMD: SMD; VAL2: 0.1W; OUMEMAKERKATAMEI: RL1632H-R001-JN; CDMASTERCADCELG: KC0020; QUADMODEL: RES_1M; GCOUNT: 1; CHIPSIZE: 3216; INSTANCENAME: INS6356
R12 = R: TIME: 13:16:51; UPDATEUSER: t5459927; SAVECOUNT: 2; ORIGINALSYMBOLORIGIN: (0,0); COMP: PRT_5; __TIME_0__: 1708057011; __FILE_0__: C:/Users/t5459927/Desktop/test_ORCtoSD/RD228-SCHEMATIC2-01/SMB007/R.smb; __HOST_0__: t5459927-02; __$Database_ID__: Z-1d8715ec-4297-42d6-bed7-916b1ffe081f; LAYOUTNAME: Z-4fe26e2d-0314-4a28-872c-3bd199d55978.cmp13; COMPONENTNAME: R_R; RESISTANCETOLER: J; FNLEADFREETHET1GT2GMCTH1: N_N_N; NOMINALRESISTAN: 1m; POWERRATING: 500m; ADSMODELNAME: s_RL1632H_R001_JN; OUMEMAKER: SSM 進工業; VAL4: KOA; OUMECLASSIFICATION: 表面実装用固定抵抗器; VAL3: RK73B1JTTD470J; MOUNTINGFORMSMD: SMD; VAL2: 0.1W; OUMEMAKERKATAMEI: RL1632H-R001-JN; CDMASTERCADCELG: KC0020; QUADMODEL: RES_1M; GCOUNT: 1; CHIPSIZE: 3216; INSTANCENAME: INS41533
R13 = R: TIME: 13:16:51; UPDATEUSER: t5459927; SAVECOUNT: 2; ORIGINALSYMBOLORIGIN: (0,0); COMP: PRT_5; __TIME_0__: 1708057011; __FILE_0__: C:/Users/t5459927/Desktop/test_ORCtoSD/RD228-SCHEMATIC2-01/SMB007/R.smb; __HOST_0__: t5459927-02; __$Database_ID__: Z-1d8715ec-4297-42d6-bed7-916b1ffe081f; LAYOUTNAME: Z-4fe26e2d-0314-4a28-872c-3bd199d55978.cmp18; COMPONENTNAME: R_R; RESISTANCETOLER: J; FNLEADFREETHET1GT2GMCTH1: N_N_N; NOMINALRESISTAN: 1m; POWERRATING: 500m; ADSMODELNAME: s_RL1632H_R001_JN; OUMEMAKER: SSM 進工業; VAL4: KOA; OUMECLASSIFICATION: 表面実装用固定抵抗器; VAL3: RK73B1JTTD470J; MOUNTINGFORMSMD: SMD; VAL2: 0.1W; OUMEMAKERKATAMEI: RL1632H-R001-JN; CDMASTERCADCELG: KC0020; QUADMODEL: RES_1M; GCOUNT: 1; CHIPSIZE: 3216; INSTANCENAME: INS45984
R14 = R: TIME: 13:16:51; UPDATEUSER: t5459927; SAVECOUNT: 2; ORIGINALSYMBOLORIGIN: (0,0); COMP: PRT_5; __TIME_0__: 1708057011; __FILE_0__: C:/Users/t5459927/Desktop/test_ORCtoSD/RD228-SCHEMATIC2-01/SMB007/R.smb; __HOST_0__: t5459927-02; __$Database_ID__: Z-1d8715ec-4297-42d6-bed7-916b1ffe081f; LAYOUTNAME: Z-4fe26e2d-0314-4a28-872c-3bd199d55978.cmp47; COMPONENTNAME: R_R; RESISTANCETOLER: J; FNLEADFREETHET1GT2GMCTH1: N_N_N; NOMINALRESISTAN: 1m; POWERRATING: 500m; ADSMODELNAME: s_RL1632H_R001_JN; OUMEMAKER: SSM 進工業; VAL4: KOA; OUMECLASSIFICATION: 表面実装用固定抵抗器; VAL3: RK73B1JTTD470J; MOUNTINGFORMSMD: SMD; VAL2: 0.1W; OUMEMAKERKATAMEI: RL1632H-R001-JN; CDMASTERCADCELG: KC0020; QUADMODEL: RES_1M; GCOUNT: 1; CHIPSIZE: 3216; INSTANCENAME: INS5242
R15 = R: TIME: 13:16:51; UPDATEUSER: t5459927; SAVECOUNT: 2; ORIGINALSYMBOLORIGIN: (0,0); COMP: PRT_5; __TIME_0__: 1708057011; __FILE_0__: C:/Users/t5459927/Desktop/test_ORCtoSD/RD228-SCHEMATIC2-01/SMB007/R.smb; __HOST_0__: t5459927-02; __$Database_ID__: Z-1d8715ec-4297-42d6-bed7-916b1ffe081f; LAYOUTNAME: Z-4fe26e2d-0314-4a28-872c-3bd199d55978.cmp15; COMPONENTNAME: R_R; RESISTANCETOLER: J; FNLEADFREETHET1GT2GMCTH1: N_N_N; NOMINALRESISTAN: 1m; POWERRATING: 500m; ADSMODELNAME: s_RL1632H_R001_JN; OUMEMAKER: SSM 進工業; VAL4: KOA; OUMECLASSIFICATION: 表面実装用固定抵抗器; VAL3: RK73B1JTTD470J; MOUNTINGFORMSMD: SMD; VAL2: 0.1W; OUMEMAKERKATAMEI: RL1632H-R001-JN; CDMASTERCADCELG: KC0020; QUADMODEL: RES_1M; GCOUNT: 1; CHIPSIZE: 3216; INSTANCENAME: INS41737
R16 = R: TIME: 13:16:51; UPDATEUSER: t5459927; SAVECOUNT: 2; ORIGINALSYMBOLORIGIN: (0,0); COMP: PRT_5; __TIME_0__: 1708057011; __FILE_0__: C:/Users/t5459927/Desktop/test_ORCtoSD/RD228-SCHEMATIC2-01/SMB007/R.smb; __HOST_0__: t5459927-02; __$Database_ID__: Z-1d8715ec-4297-42d6-bed7-916b1ffe081f; LAYOUTNAME: Z-4fe26e2d-0314-4a28-872c-3bd199d55978.cmp11; COMPONENTNAME: R_R; RESISTANCETOLER: J; FNLEADFREETHET1GT2GMCTH1: N_N_N; NOMINALRESISTAN: 1m; POWERRATING: 500m; ADSMODELNAME: s_RL1632H_R001_JN; OUMEMAKER: SSM 進工業; VAL4: KOA; OUMECLASSIFICATION: 表面実装用固定抵抗器; VAL3: RK73B1JTTD470J; MOUNTINGFORMSMD: SMD; VAL2: 0.1W; OUMEMAKERKATAMEI: RL1632H-R001-JN; CDMASTERCADCELG: KC0020; QUADMODEL: RES_1M; GCOUNT: 1; CHIPSIZE: 3216; INSTANCENAME: INS46178
R17 = R: TIME: 13:16:51; UPDATEUSER: t5459927; SAVECOUNT: 2; ORIGINALSYMBOLORIGIN: (0,0); COMP: PRT_8; __TIME_0__: 1708057011; __FILE_0__: C:/Users/t5459927/Desktop/test_ORCtoSD/RD228-SCHEMATIC2-01/SMB007/R.smb; __HOST_0__: t5459927-02; __$Database_ID__: Z-1d8715ec-4297-42d6-bed7-916b1ffe081f; LAYOUTNAME: Z-4fe26e2d-0314-4a28-872c-3bd199d55978.cmp46; COMPONENTNAME: R_R; RESISTANCETOLER: J; FNLEADFREETHET1GT2GMCTH1: N_N_N; NOMINALRESISTAN: 10K; POWERRATING: 100m; ADSMODELNAME: s_RK73B1JTTD103J@@; OUMEMAKER: KOA コーア; VAL4: KOA; OUMECLASSIFICATION: 表面実装用固定抵抗器; VAL3: RK73B1ETTP912J; MOUNTINGFORMSMD: SMD; VAL2: 0.1W; OUMEMAKERKATAMEI: RK73B1JTTD103J@@; CDMASTERCADCELG: KC0133; QUADMODEL: RES_10K; GCOUNT: 1; INSTANCENAME: INS5742
R18 = R: TIME: 13:16:51; UPDATEUSER: t5459927; SAVECOUNT: 2; ORIGINALSYMBOLORIGIN: (0,0); COMP: PRT_8; __TIME_0__: 1708057011; __FILE_0__: C:/Users/t5459927/Desktop/test_ORCtoSD/RD228-SCHEMATIC2-01/SMB007/R.smb; __HOST_0__: t5459927-02; __$Database_ID__: Z-1d8715ec-4297-42d6-bed7-916b1ffe081f; LAYOUTNAME: Z-4fe26e2d-0314-4a28-872c-3bd199d55978.cmp50; COMPONENTNAME: R_R; RESISTANCETOLER: J; FNLEADFREETHET1GT2GMCTH1: N_N_N; NOMINALRESISTAN: 10K; POWERRATING: 100m; ADSMODELNAME: s_RK73B1JTTD103J@@; OUMEMAKER: KOA コーア; VAL4: KOA; OUMECLASSIFICATION: 表面実装用固定抵抗器; VAL3: RK73B1ETTP912J; MOUNTINGFORMSMD: SMD; VAL2: 0.1W; OUMEMAKERKATAMEI: RK73B1JTTD103J@@; CDMASTERCADCELG: KC0133; QUADMODEL: RES_10K; GCOUNT: 1; INSTANCENAME: INS41807
R19 = R: TIME: 13:16:51; UPDATEUSER: t5459927; SAVECOUNT: 2; ORIGINALSYMBOLORIGIN: (0,0); COMP: PRT_8; __TIME_0__: 1708057011; __FILE_0__: C:/Users/t5459927/Desktop/test_ORCtoSD/RD228-SCHEMATIC2-01/SMB007/R.smb; __HOST_0__: t5459927-02; __$Database_ID__: Z-1d8715ec-4297-42d6-bed7-916b1ffe081f; LAYOUTNAME: Z-4fe26e2d-0314-4a28-872c-3bd199d55978.cmp45; COMPONENTNAME: R_R; RESISTANCETOLER: J; FNLEADFREETHET1GT2GMCTH1: N_N_N; NOMINALRESISTAN: 10K; POWERRATING: 100m; ADSMODELNAME: s_RK73B1JTTD103J@@; OUMEMAKER: KOA コーア; VAL4: KOA; OUMECLASSIFICATION: 表面実装用固定抵抗器; VAL3: RK73B1ETTP912J; MOUNTINGFORMSMD: SMD; VAL2: 0.1W; OUMEMAKERKATAMEI: RK73B1JTTD103J@@; CDMASTERCADCELG: KC0133; QUADMODEL: RES_10K; GCOUNT: 1; INSTANCENAME: INS46240
R20 = R: TIME: 13:16:51; UPDATEUSER: t5459927; SAVECOUNT: 2; ORIGINALSYMBOLORIGIN: (0,0); COMP: PRT_5; __TIME_0__: 1708057011; __FILE_0__: C:/Users/t5459927/Desktop/test_ORCtoSD/RD228-SCHEMATIC2-01/SMB007/R.smb; __HOST_0__: t5459927-02; __$Database_ID__: Z-1d8715ec-4297-42d6-bed7-916b1ffe081f; LAYOUTNAME: Z-4fe26e2d-0314-4a28-872c-3bd199d55978.cmp19; COMPONENTNAME: R_R; RESISTANCETOLER: J; FNLEADFREETHET1GT2GMCTH1: N_N_N; NOMINALRESISTAN: 1m; POWERRATING: 500m; ADSMODELNAME: s_RL1632H_R001_JN; OUMEMAKER: SSM 進工業; VAL4: KOA; OUMECLASSIFICATION: 表面実装用固定抵抗器; VAL3: RK73B1ETTP470J; MOUNTINGFORMSMD: SMD; VAL2: 0.1W; OUMEMAKERKATAMEI: RL1632H-R001-JN; CDMASTERCADCELG: KC0020; QUADMODEL: RES_1M; GCOUNT: 1; CHIPSIZE: 3216; INSTANCENAME: INS78910
R21 = R: TIME: 13:16:51; UPDATEUSER: t5459927; SAVECOUNT: 2; ORIGINALSYMBOLORIGIN: (0,0); COMP: PRT_8; __TIME_0__: 1708057011; __FILE_0__: C:/Users/t5459927/Desktop/test_ORCtoSD/RD228-SCHEMATIC2-01/SMB007/R.smb; __HOST_0__: t5459927-02; __$Database_ID__: Z-1d8715ec-4297-42d6-bed7-916b1ffe081f; LAYOUTNAME: Z-4fe26e2d-0314-4a28-872c-3bd199d55978.cmp6; COMPONENTNAME: R_R; RESISTANCETOLER: J; FNLEADFREETHET1GT2GMCTH1: N_N_N; NOMINALRESISTAN: 10K; POWERRATING: 100m; ADSMODELNAME: s_RK73B1JTTD103J@@; OUMEMAKER: KOA コーア; VAL4: SSM; OUMECLASSIFICATION: 表面実装用固定抵抗器; VAL3: PRL3264-R010-F-T1; MOUNTINGFORMSMD: SMD; MAKER: KOA; VAL2: 2W; OUMEMAKERKATAMEI: RK73B1JTTD103J@@; CDMASTERCADCELG: KC0133; QUADMODEL: RES_10K; GCOUNT: 1; CHIPSIZE: 1608; INSTANCENAME: INS10514
RT1 = VARA_0: OUMEPARTTYPE: RV; TIME: 09:56:50; UPDATEUSER: tomizawa-y; SAVECOUNT: 12; COMP: PRT_37; SAVEAREA0: -9950,-8554,25168,13619; ORIGINALSYMBOLORIGIN: (0,0); __TIME_0__: 1708057012; __USER_0__: t5459927; __FILE_0__: C:/Users/t5459927/Desktop/test_ORCtoSD/RD228-SCHEMATIC2-01/RD228_SMCD_RM______/VARA_0.smb; __HOST_0__: t5459927-02; __$Database_ID__: Z-830099c9-1790-46fb-9e01-bc8e5a804c28; LAYOUTNAME: Z-4fe26e2d-0314-4a28-872c-3bd199d55978.cmp2; COMPONENTNAME: VARA_0_VARA_0; RATEDVOLTAGE: 0; CDMASTERCADCELG: KC0008; MAKER: NIPPON CHEMICON; GCOUNT: 1; OUMEMAKER: TDK ＴＤＫ; MOUNTINGFORMSMD: SMD; VAL4: TDK; FNLEADFREETHET1GT2GMCTH1: N_N_N; VAL2: R1005; VAL1: NTC 10k; OUMECLASSIFICATION: バリスタ; OUMEMAKERKATAMEI: AVR-M1608C220KT6AB; INSTANCENAME: INS13125
U3 = WAKU_DEF100: TIME: 14:30:25; UPDATEUSER: cae; UPDATETIME: 13:16:51; SAVECOUNT: 3; PLOTTIME: HH:MM; SAVEAREA0: -63393,-16950,474261,314592; ORIGINALSYMBOLORIGIN: (0,0); LAYOUTNAME: Z-4fe26e2d-0314-4a28-872c-3bd199d55978.cmp49; NOTMOUNT: MOUNT; DESIGNED: TOSHIBA; INSTANCENAME: INS88674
